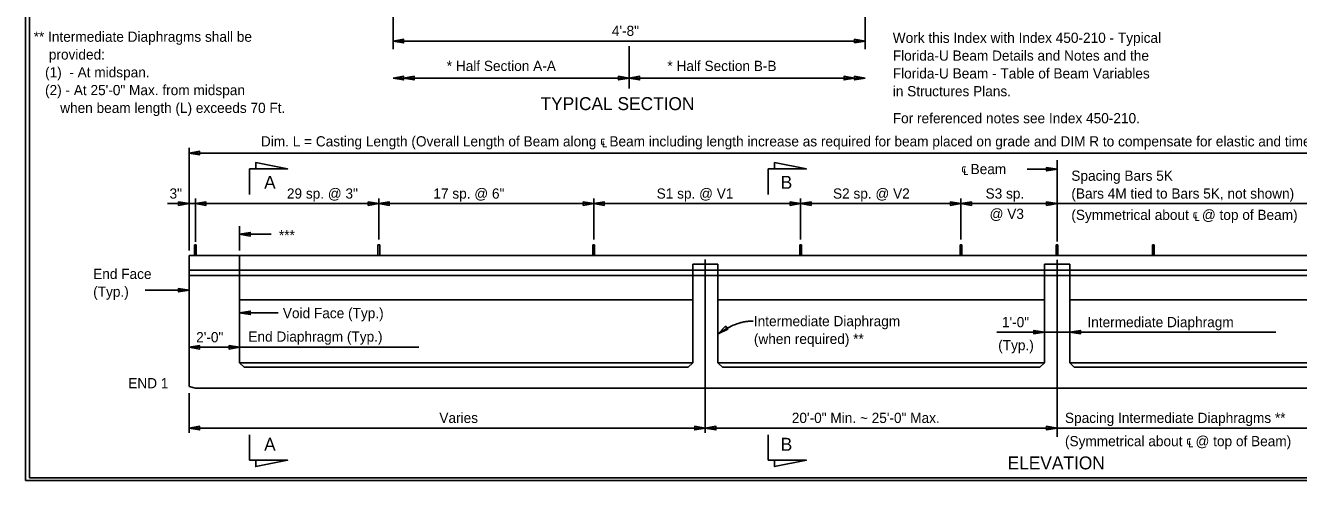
# Model space of a CAD drawing. Extents: x 0 to 20.5, y 0 to 12.9.
# Drawn here: x -0.04 to 12.54, y -0.03 to 4.48 of the extents above; entities that cross this region are included whole.
import ezdxf

# ---------------------------------------------------------------- set-up
doc = ezdxf.new("R2010")
doc.units = 0
for name, color, linetype in [('ActivePts-ConstElements', 7, 'Continuous'), ('BeamConc', 7, 'Continuous'), ('BeamConc_h', 7, 'Continuous'), ('CL_Major', 7, 'Continuous'), ('Dimension', 7, 'Continuous'), ('Miscellaneous1', 7, 'Continuous'), ('Rebar', 7, 'Continuous'), ('TextStructures', 7, 'Continuous')]:
    doc.layers.add(name, color=color, linetype=linetype)

# ---------------------------------------------------------------- blocks, each defined once
blk = doc.blocks.new('ALT')
at = {"layer": 'Dimension'}
for points in [[(0, 0), (-0.00041, -0.000069), (-0.00041, 0.000069)], [(-0.000121, 0), (-0.000397, -0.000043), (-0.000397, 0.000043)], [(-0.000233, 0), (-0.000374, -0.000023), (-0.000374, 0.000023)]]:
    blk.add_lwpolyline(points, close=True, dxfattribs=at)

msp = doc.modelspace()

# ---------------------------------------------------------------- linework, layer by layer
at = {"layer": 'ActivePts-ConstElements'}
msp.add_lwpolyline([(-0.04, -0.026), (20.485, -0.026), (20.485, 12.947), (-0.04, 12.947)], close=True, dxfattribs=at)
at = {"layer": 'BeamConc'}
for p, q in [((1.577, 0.903), (1.577, 2.199)), ((19.112, 2.199), (1.577, 2.199)), ((1.577, 2.054), (19.112, 2.054)), ((1.577, 2.004), (19.112, 2.004)), ((1.577, 0.903), (1.639, 0.887)), ((1.639, 0.887), (19.05, 0.887))]:
    msp.add_line(p, q, dxfattribs=at)
at = {"layer": 'BeamConc_h'}
for p, q in [((2.077, 1.139), (2.077, 2.199)), ((6.555, 2.116), (6.805, 2.116)), ((6.555, 2.116), (6.555, 1.139)), ((6.805, 2.116), (6.805, 1.139)), ((10.033, 2.116), (10.283, 2.116)), ((10.033, 2.116), (10.033, 1.139)), ((10.283, 2.116), (10.283, 1.139)), ((2.077, 1.762), (6.555, 1.762)), ((6.805, 1.762), (10.033, 1.762)), ((10.283, 1.762), (13.51, 1.762)), ((2.121, 1.095), (2.077, 1.139)), ((2.077, 1.139), (6.555, 1.139)), ((6.511, 1.095), (6.555, 1.139)), ((6.805, 1.139), (10.033, 1.139)), ((6.85, 1.095), (6.805, 1.139)), ((9.988, 1.095), (10.033, 1.139)), ((10.283, 1.139), (13.51, 1.139)), ((10.327, 1.095), (10.283, 1.139)), ((2.121, 1.095), (6.511, 1.095)), ((6.85, 1.095), (9.988, 1.095)), ((10.327, 1.095), (13.465, 1.095))]:
    msp.add_line(p, q, dxfattribs=at)
at = {"layer": 'CL_Major'}
for p, q in [((5.926, 3.853), (5.926, 4.272)), ((10.158, 2.339), (10.158, 3.143)), ((6.68, 0.446), (6.68, 2.162)), ((10.158, 0.406), (10.158, 2.156))]:
    msp.add_line(p, q, dxfattribs=at)
at = {"layer": 'Dimension'}
for p, q in [((3.593, 4.241), (3.593, 4.598)), ((8.26, 4.241), (8.26, 4.598)), ((3.593, 4.321), (8.26, 4.321)), ((3.593, 3.955), (8.26, 3.955)), ((1.577, 2.25), (1.577, 3.264)), ((1.577, 3.213), (19.112, 3.213)), ((2.174, 2.805), (2.174, 3.056)), ((2.174, 3.056), (2.55, 3.056)), ((2.55, 3.056), (2.236, 3.119)), ((2.236, 3.119), (2.236, 3.056)), ((7.302, 2.805), (7.302, 3.056)), ((7.302, 3.056), (7.679, 3.056)), ((7.679, 3.056), (7.365, 3.119)), ((7.365, 3.119), (7.365, 3.056)), ((10.158, 3.054), (9.86, 3.054)), ((1.363, 2.713), (13.376, 2.713)), ((1.639, 2.337), (1.639, 2.764)), ((3.452, 2.357), (3.452, 2.764)), ((5.577, 2.357), (5.577, 2.764)), ((7.622, 2.357), (7.622, 2.764)), ((9.207, 2.357), (9.207, 2.764)), ((2.077, 2.25), (2.077, 2.491)), ((2.39, 2.41), (2.077, 2.41)), ((1.144, 1.858), (1.577, 1.858)), ((2.457, 1.633), (2.077, 1.633)), ((12.318, 1.441), (9.561, 1.441)), ((1.577, 1.292), (3.849, 1.292)), ((1.577, 0.446), (1.577, 0.839)), ((1.577, 0.493), (13.244, 0.493)), ((2.174, 0.426), (2.174, 0.175)), ((7.302, 0.426), (7.302, 0.175)), ((2.174, 0.175), (2.55, 0.175)), ((2.55, 0.175), (2.236, 0.112)), ((2.236, 0.112), (2.236, 0.175)), ((7.302, 0.175), (7.679, 0.175)), ((7.679, 0.175), (7.365, 0.112)), ((7.365, 0.112), (7.365, 0.175))]:
    msp.add_line(p, q, dxfattribs=at)
for points in [[(8.26, 4.321), (8.156, 4.339), (8.156, 4.304)], [(3.593, 3.955), (3.697, 3.937), (3.697, 3.973)], [(3.697, 3.955), (3.801, 3.937), (3.801, 3.973)], [(5.926, 3.955), (5.822, 3.973), (5.822, 3.937)], [(5.926, 3.955), (6.03, 3.973), (6.03, 3.937)], [(8.156, 3.955), (8.051, 3.973), (8.051, 3.937)], [(8.26, 3.955), (8.156, 3.973), (8.156, 3.937)], [(1.577, 3.213), (1.681, 3.196), (1.681, 3.231)], [(2.236, 3.056), (2.236, 3.119), (2.55, 3.056)], [(7.365, 3.056), (7.365, 3.119), (7.679, 3.056)], [(10.158, 3.054), (10.053, 3.071), (10.053, 3.036)], [(1.577, 2.713), (1.473, 2.696), (1.473, 2.731)], [(1.639, 2.713), (1.744, 2.696), (1.744, 2.731)], [(3.452, 2.713), (3.348, 2.696), (3.348, 2.731)], [(3.452, 2.713), (3.556, 2.696), (3.556, 2.731)], [(5.577, 2.713), (5.473, 2.696), (5.473, 2.731)], [(5.577, 2.713), (5.681, 2.696), (5.681, 2.731)], [(7.622, 2.713), (7.517, 2.696), (7.517, 2.731)], [(7.622, 2.713), (7.726, 2.696), (7.726, 2.731)], [(9.206, 2.713), (9.102, 2.696), (9.102, 2.731)], [(9.206, 2.713), (9.311, 2.696), (9.311, 2.731)], [(10.157, 2.713), (10.053, 2.696), (10.053, 2.731)], [(2.077, 2.41), (2.181, 2.393), (2.181, 2.428)], [(1.577, 1.858), (1.473, 1.875), (1.473, 1.84)], [(2.077, 1.633), (2.181, 1.616), (2.181, 1.651)], [(6.806, 1.425), (6.901, 1.471), (6.881, 1.5)], [(10.033, 1.441), (9.928, 1.459), (9.928, 1.424)], [(10.283, 1.441), (10.387, 1.424), (10.387, 1.459)], [(1.577, 1.292), (1.681, 1.274), (1.681, 1.309)], [(2.077, 1.292), (1.973, 1.274), (1.973, 1.309)], [(1.577, 0.493), (1.681, 0.476), (1.681, 0.511)], [(6.68, 0.493), (6.576, 0.476), (6.576, 0.511)], [(6.68, 0.493), (6.785, 0.476), (6.785, 0.511)], [(10.158, 0.493), (10.053, 0.511), (10.053, 0.476)], [(2.236, 0.175), (2.236, 0.112), (2.55, 0.175)], [(7.365, 0.175), (7.365, 0.112), (7.679, 0.175)]]:
    msp.add_lwpolyline(points, close=True, dxfattribs=at)
msp.add_open_spline([(7.153, 1.552), (6.984, 1.552), (6.806, 1.425)], degree=2, dxfattribs=at)
at = {"layer": 'Miscellaneous1'}
msp.add_lwpolyline([(0, 12.947), (20.485, 12.947), (20.485, 0), (0, 0)], close=True, dxfattribs=at)
at = {"layer": 'Rebar'}
for p, q in [((1.648, 2.307), (1.631, 2.307)), ((1.631, 2.307), (1.631, 2.2)), ((1.648, 2.2), (1.648, 2.307)), ((3.461, 2.307), (3.443, 2.307)), ((3.443, 2.307), (3.443, 2.2)), ((3.461, 2.2), (3.461, 2.307)), ((5.586, 2.307), (5.568, 2.307)), ((5.568, 2.307), (5.568, 2.2)), ((5.586, 2.2), (5.586, 2.307)), ((7.63, 2.307), (7.613, 2.307)), ((7.613, 2.307), (7.613, 2.2)), ((7.63, 2.2), (7.63, 2.307)), ((9.215, 2.307), (9.198, 2.307)), ((9.198, 2.307), (9.198, 2.2)), ((9.215, 2.2), (9.215, 2.307)), ((10.149, 2.2), (10.149, 2.307)), ((10.149, 2.307), (10.166, 2.307)), ((10.166, 2.307), (10.166, 2.2)), ((11.1, 2.2), (11.1, 2.307)), ((11.1, 2.307), (11.117, 2.307)), ((11.117, 2.307), (11.117, 2.2))]:
    msp.add_line(p, q, dxfattribs=at)

# ---------------------------------------------------------------- block references
at = {"layer": 'Dimension', "xscale": 254, "yscale": 255.88988095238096, "rotation": 180}
msp.add_blockref('ALT', (3.593, 4.321), dxfattribs=at)
msp.add_blockref('ALT', (3.593, 4.321), dxfattribs=at)
at = {"layer": 'Dimension', "xscale": 164.50777202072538, "yscale": 167.927734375}
msp.add_blockref('ALT', (10.158, 2.713), dxfattribs=at)
msp.add_blockref('ALT', (10.158, 2.713), dxfattribs=at)

# ---------------------------------------------------------------- texts
at = {"layer": 'Dimension'}
for s, p in [('** Intermediate Diaphragms shall be', (0.041, 4.314)), ('  Work this Index with Index 450-210 - Typical', (8.458, 4.303)), ('    provided:', (0.041, 4.138)), ('  Florida-U Beam Details and Notes and the', (8.458, 4.127)), ('   (1)  - At midspan.', (0.041, 3.962)), ('  Florida-U Beam - Table of Beam Variables', (8.458, 3.951)), ('   (2) - At 25\'-0" Max. from midspan', (0.041, 3.786)), ('  in Structures Plans.', (8.458, 3.775)), ('       when beam length (L) exceeds 70 Ft.', (0.041, 3.61)), ('Spacing Bars 5K', (10.298, 2.939)), ('(Bars 4M tied to Bars 5K, not shown)', (10.298, 2.763)), ('End Face', (0.629, 1.968)), ('(Typ.)', (0.629, 1.792)), ('Intermediate Diaphragm ', (7.16, 1.501)), ('(when required) **', (7.16, 1.325))]:
    msp.add_text(s, height=0.1008, dxfattribs=at).set_placement(p)
at = {"layer": 'TextStructures'}
for s, height, p in [('4\'-8"', 0.1008, (5.756, 4.372)), ('* Half Section A-A', 0.1008, (4.124, 4.025)), ('* Half Section B-B', 0.1008, (6.305, 4.025)), ('TYPICAL SECTION', 0.128, (5.051, 3.638)), ('  For referenced notes see Index 450-210.', 0.1008, (8.458, 3.508)), ('Dim. L = Casting Length (Overall Length of Beam along ℄ Beam including length increase as required for beam placed on grade and DIM R to compensate for elastic and time dependent shortening effects)', 0.1008, (2.287, 3.279)), ('℄ Beam', 0.1008, (9.21, 3.005)), ('A', 0.128, (2.319, 2.86)), ('B', 0.128, (7.425, 2.86)), ('3"', 0.1008, (1.384, 2.763)), ('29 sp. @ 3"', 0.1008, (2.544, 2.763)), ('17 sp. @ 6"', 0.1008, (3.992, 2.763)), ('S1 sp. @ V1', 0.1008, (6.199, 2.763)), ('S2 sp. @ V2', 0.1008, (7.942, 2.763)), ('S3 sp.', 0.1008, (9.45, 2.763)), ('@ V3', 0.1008, (9.49, 2.562)), ('(Symmetrical about ℄ @ top of Beam)', 0.1008, (10.298, 2.552)), ('***', 0.1008, (2.465, 2.35)), ('Void Face (Typ.)', 0.1008, (2.504, 1.58)), ('1\'-0"', 0.1008, (9.612, 1.491)), ('Intermediate Diaphragm ', 0.1008, (10.457, 1.491)), ('2\'-0"', 0.1008, (1.647, 1.342)), ('End Diaphragm (Typ.)', 0.1008, (2.163, 1.348)), ('(Typ.)', 0.1008, (9.575, 1.263)), ('END 1', 0.1008, (0.976, 0.887)), ('Varies ', 0.1008, (4.051, 0.544)), ('20\'-0" Min. ~ 25\'-0" Max. ', 0.1008, (7.535, 0.544)), ('Spacing Intermediate Diaphragms **', 0.1008, (10.235, 0.544)), ('A', 0.128, (2.319, 0.269)), ('B', 0.128, (7.425, 0.269)), ('(Symmetrical about ℄ @ top of Beam)', 0.1008, (10.235, 0.314)), ('ELEVATION', 0.128, (9.668, 0.085))]:
    msp.add_text(s, height=height, dxfattribs=at).set_placement(p)

doc.saveas('drawing.dxf')
